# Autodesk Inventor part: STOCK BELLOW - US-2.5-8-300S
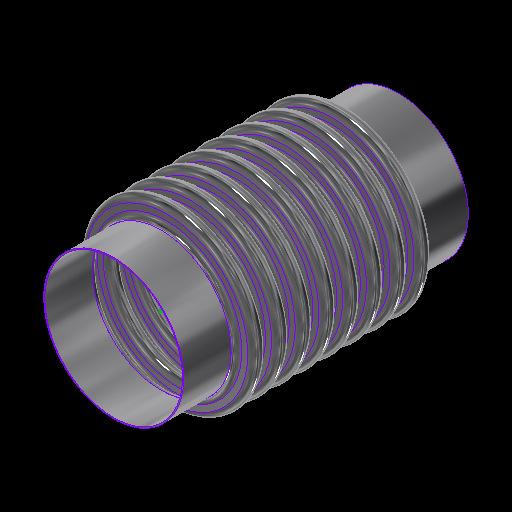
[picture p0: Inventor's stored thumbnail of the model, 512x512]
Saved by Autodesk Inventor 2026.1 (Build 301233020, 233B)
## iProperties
Category: 24 GA (0.024 THICK)
RuleStatus: InUse
Created: 2024-01
Part Number: STOCK BELLOW - US-2.5-8-300S
Project: =STOCK BELLOWS: <Stock Number><SFILL>
Material: ASTM A240-304
Description: =STOCK BELLOWS: <Stock Number>, <SID_> I.D., <SOD_> O.D., <SPLY_> PLY, <Category>, <SNET_CONS> CONS.<PITCH_><STANGENT_> TANGENT<SFILL>
Document SubType Name: Sheet Metal
Designer: GS
Stock Number: U.S-2.5-8-300S
Surface Area: 1355.78 cm^2
Volume: 41.0641 cm^3
Sheet Metal Rule: Default
Appearance: STAINLESS STEEL
Mass: 330.865 g
Density: 8.05729 g/cm^3
THK: 0.036
ID: 3.500
OD: 4.250
CONS_: 2
PITCH: 0.500
TANGENT: 0.500
BELLOWS_UPSET: 0.000
d79: 1.000
d82: 1.000
d83: 26.000
d84: 24.000
d174: 8
d214: 8
STHK_: 0.024
SID_: 2.900
SOD_: 3.700
SPITCH_: 0.500
STANGENT__: 1.000
SBELLOWS_UPSET_: 0.000
SDIFF_TAN: 1.000
d252: 2
d275: 2
d287: 0.050
d289: 0.500
d290: 0.000
SOD_NECK: 2 15/16
PLY: 1
PSET: 4.178
PBAR: 1.035
COUNTER: 1.500
NET_TUBE: 3.071
CONS: 2
S_CONS: 0
NET_CONS: 2
ID_M: 88.90 mm
OD_M: 107.95 mm
THK_M: 0.91 mm
ID_U: 3.500 in
OD_U: 4.250 in
THK_U: 0.036 in
TANGENT2: 0.500
TAN_TO_TAN: 1.000 in
d80: 2.571
d81: 10
SID: 2.375
SCONS_: 8
SPITCH: 0.250
STANGENT_: 1.000
SBELLOWS_UPSET: 0.000
SNET_CONS: 8
SS_CONS: 0
SCONS: 8
d190: 8
d191: 1
d192: 1
d193: 8
d194: 0
SIZE: 2.50
PRESSURE: 300
d230: 8
STANGENT: 4.000
SPLY_: 1
d233: 8
d234: 0
d263: 2
d265: 1
d268: 2
d269: 0
d286: 2
d288: 1
d291: 2
d292: 0
SREROLL: 0.750
BLETP: 0.000 ul
PRES_Copy: 85
MATTABLE: 20 GA (0.036 THICK)
PART_NUMBER: U.S-2.5-8-300S
PITCH_: =, <SPITCH_> PITCH,
CFILL: .
SFILL: .
MESH: ,
COMP: 0.77
EXT: 0.39
LAT: 0.30
ANG: 573
ASR: 1441
LSR: 1471
ANSR: 53
PRES: 300
COMPM: 7.7
EXTM: 3.85
LATM: 3.00
ASRM: 252.362
PRESM: 20.684
LSRM: 257.616
ANSRM: 9.282
TEMPMIN: 20
TEMPMAX: 800
TEMPMINM: -7
TEMPMAXM: 427
WEIGHTM: 0.331
WEIGHT: 0.729
Author: GS
Keywords: 20 GA (0.036 THICK)
Comments: =STOCK BELLOW - <STOCK NUMBER>
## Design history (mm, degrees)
sketch "Sketch2"
  geometry: L1 (0, -177.245)-(0, 562.856) reference; L2 (45.364, 0)-(44.45, 0); L3 (48.082, -2.718)-(50.343, -2.718); L4 (48.082, -3.632)-(50.343, -3.632); L5 (50.343, -9.982)-(48.082, -9.982); L6 (50.343, -9.068)-(48.082, -9.068); L7 (45.364, -12.7)-(44.45, -12.7); L8 (48.082, 0)-(48.082, -12.7); L9 (50.343, -6.35)-(53.975, -6.35); L10 (44.45, 0)-(44.45, -12.7); L11 (20.376, 102.841)-(20.376, 101.926); L12 (58.262, 457.127)-(58.262, 349.177); L13 (58.262, 444.427)-(58.262, 336.477); L14 (93.133, -58.817)-(93.133, -71.517); L15 (118.746, -66.401)-(118.746, -66.401); L16 (50.343, -9.068)-(50.343, -9.982); L17 (48.082, -9.068)-(48.082, -9.982); L18 (48.082, -9.525)-(50.343, -9.525); L19 (53.975, 0)-(53.975, -12.7); L20 (-50.343, -9.068)-(-50.343, -9.982); L21 (-50.343, -2.718)-(-48.082, -2.718); L22 (-50.343, -3.632)-(-48.082, -3.632); L23 (-48.082, -9.068)-(-50.343, -9.068); L24 (-50.343, -9.525)-(-48.082, -9.525); L25 (-48.082, -9.982)-(-50.343, -9.982); L26 (-48.082, -9.068)-(-48.082, -9.982); L27 (-44.45, 0.653)-(-44.45, -12.047); L28 (-48.082, -6.35)-(-44.45, -6.35); L29 (-50.343, 0.653)-(-50.343, -12.7); L30 (-53.061, 0)-(-53.975, 0); L31 (-53.975, 0)-(-53.975, -12.7); L32 (-53.061, -12.7)-(-53.975, -12.7); A1 r 2.718 centre (48.082, 0) between (45.364, 0) and (48.082, -2.718); A2 r 3.632 centre (48.082, 0) between (44.45, 0) and (48.082, -3.632); A3 r 3.632 centre (50.343, -6.35) between (50.343, -9.982) and (50.343, -2.718); A4 r 2.718 centre (50.343, -6.35) between (50.343, -9.068) and (50.343, -3.632); A5 r 2.718 centre (48.082, -12.7) between (48.082, -9.982) and (45.364, -12.7); A6 r 3.632 centre (48.082, -12.7) between (48.082, -9.068) and (44.45, -12.7); A7 r 3.175 centre (50.343, -6.35) between (50.343, -9.525) and (53.518, -6.35); A8 r 3.175 centre (48.082, -12.7) between (48.082, -9.525) and (44.907, -12.7); A9 r 2.718 centre (-50.343, -12.7) between (-50.343, -9.982) and (-53.061, -12.7); A10 r 2.718 centre (-48.082, -6.35) between (-48.082, -9.068) and (-48.082, -3.632); A11 r 3.175 centre (-48.082, -6.35) between (-48.082, -9.525) and (-44.907, -6.35); A12 r 3.632 centre (-48.082, -6.35) between (-48.082, -9.982) and (-48.082, -2.718); A13 r 3.175 centre (-50.343, -12.7) between (-50.343, -9.525) and (-53.518, -12.7); A14 r 3.632 centre (-50.343, -12.7) between (-50.343, -9.068) and (-53.975, -12.7); A15 r 2.718 centre (-50.343, 0) between (-53.061, 0) and (-50.343, -2.718); A16 r 3.632 centre (-50.343, 0) between (-53.975, 0) and (-50.343, -3.632); 10 further points
  constraints: 62 end point, 38 point on circle, 20 tangent, 16 centre point, 12 parallel, 9 midpoint, 7 vertical, 6 coincident, 6 concentric, 6 point on line, 4 equal radius, 4 perpendicular, 3 horizontal, 1 collinear, 1 horizontal alignment, 10 other
  dimensions: "THK" = 0.9144 distance of L11.start L11.end; "ID" = 88.9 distance of L11.end point (20.376, 13.026); "OD" = 107.95 distance of L12.start L12.end; "PITCH" = 12.7 distance of L12.start L13.start; "TANGENT" = 12.7 distance of L14.start L14.end; "BELLOWS_UPSET" = 0 distance of L15.start L15.end; "d43" = 88.9 diameter of L10 L1 (= ID); "d44" = 107.95 diameter of L9.end L1 (= OD); "d45" = 0.9144 distance between parallel lines of L5 L6 (computed from THK, PLY); "d46" = 3.6322 radius of A3 (computed from PITCH, THK, PLY); "UPSET_PITCH" = 12.7 distance of L2.end L7.end (derived); "SIDEWALL_ANGLE" = 360 deg dimension on L3 L9 (derived); "CON_GAP" = 5.4356 distance of point (48.082, -9.068) point (48.082, -3.632) (derived); "TAN1" = 4.98728 dimension on A8 (derived); "TAN2" = 4.98728 dimension on A7 (derived); "LEG1" = 2.2606 distance of L18.start L18.end (derived); "d278" = 0.9144 distance between parallel lines of L25 L23 (derived); "d279" = 3.6322 radius of A12 (derived); "d280" = 12.7 distance of L30.end L31.end (derived); "d281" = 360 deg dimension on L21 L28 (derived); "d282" = 5.4356 distance of point (-50.343, -9.068) point (-50.343, -3.632) (derived); "d283" = 4.98728 dimension on A13 (derived); "d284" = 4.98728 dimension on A11 (derived); "d285" = 2.2606 distance of L24.start L24.end (derived); "d293" = 88.9 diameter of L27 L1 (derived); "d294" = 107.95 diameter of L31 L1 (derived)
  node "Sketch Rectangular Pattern1" dims "d31" = 25.4, "ID" = 88.9
  node "Sketch Rectangular Pattern2" dims "d39" = 25.4, "PITCH" = 12.7
revolve "CONS" stored, may be unused: angle "d48" = 90 deg
node "BELLOW MIDPLANE"
pattern_linear "Rectangular Pattern2" dims "d52" = 12.7 (= UPSET_PITCH)
sketch "Sketch5"
  geometry: C1 r 45.364 at (0, 0) reference; C2 r 44.45 at (0, 0) reference
extrude "TANGENT" new body sketch "Sketch5" distance "d53" = 12.7 (= TANGENT); taper "d54" = 0 deg
revolve "SAMETAN" stored, may be unused: angle "d65" = 90 deg
revolve "DIFFTAN" stored, may be unused: angle "d70" = 90 deg
sketch "Sketch9"
  geometry: L1 (53.319, 0)-(-53.319, 0) reference; L2 (0, -17.78)-(0, 17.78) reference; L3 (38.085, 0)-(-38.085, 0); L4 (38.085, -11.906)-(38.085, 11.906); L5 (25.385, -11.906)-(25.385, 11.906); L6 (13.15, 11.906)-(13.15, -11.906); L7 (-25.385, -11.906)-(-25.385, 11.906); L8 (-38.085, -11.906)-(-38.085, 11.906); L9 (37.291, -11.906)-(37.291, 11.906); L10 (38.085, -11.906)-(37.291, -11.906); L11 (38.085, 11.906)-(37.291, 11.906); L12 (13.546, 11.906)-(12.753, 11.906); L13 (12.753, 11.906)-(12.753, -11.906); L14 (12.753, -11.906)-(13.546, -11.906); L15 (13.546, -11.906)-(13.546, 11.906); L16 (-13.546, 11.906)-(-13.546, -11.906); L17 (-13.15, 11.906)-(-13.15, -11.906); L18 (-13.546, -11.906)-(-12.753, -11.906); L19 (-12.753, -11.906)-(-12.753, 11.906); L20 (-12.753, 11.906)-(-13.546, 11.906); L21 (-38.085, -11.906)-(-37.291, -11.906); L22 (-37.291, -11.906)-(-37.291, 11.906); L23 (-37.291, 11.906)-(-38.085, 11.906); L24 (-38.085, 11.906)-(-38.085, -11.906); L25 (38.085, -0.397)-(-38.085, -0.397); L26 (-38.085, -0.397)-(-38.085, 0.397); L27 (-38.085, 0.397)-(38.085, 0.397); L28 (38.085, 0.397)-(38.085, -0.397); L29 (-38.085, 11.906)-(38.085, 11.906); L30 (38.085, 11.906)-(38.085, 12.7); L31 (38.085, 12.7)-(-38.085, 12.7); L32 (-38.085, 12.7)-(-38.085, 11.906); L33 (38.085, -11.906)-(-38.085, -11.906); L34 (-38.085, -11.906)-(-38.085, -12.7); L35 (-38.085, -12.7)-(38.085, -12.7); L36 (38.085, -12.7)-(38.085, -11.906); 30 further points
  constraints: 68 end point, 13 midpoint, 13 parallel, 8 horizontal, 7 perpendicular, 6 equal length, 3 point on line, 2 vertical, 14 other
  dimensions: "d115" = 23.8125 distance of L4.start L4.end (derived); "d116" = 12.7 distance between parallel lines of L4 L5 (derived); "d117" = 12.23516 distance between parallel lines of L5 L6 (derived); "d125" = 38.53427 distance between parallel lines of L7 L6 (derived); "d127" = 12.7 distance between parallel lines of L8 L7 (derived); "d128" = 24.93516 distance between parallel lines of L6 L4 (derived); "d130" = 76.16943 distance between parallel lines of L8 L4 (derived); "RULER_THK" = 0.79375 distance between parallel lines of L4 L9; "d135" = 0.79375 distance of L13.end L14.end (derived); "d138" = 26.29911 distance of L13.end L16.end (derived); "d143" = 0.79375 distance of L22.end L8.end (derived); "d144" = 0.79375 distance between parallel lines of L27 L25 (derived)
extrude "RULER" join sketch "Sketch9" distance "d149" = 0.79375 (derived); taper "d150" = 0 deg
extrude "BARS" join sketch "Sketch9" distance "d151" = 0.79375 (derived); taper "d152" = 0 deg
pattern_linear "Rectangular Pattern4" dims "d155" = 26.29911 (derived)
sketch "Sketch13"
  geometry: L1 (93.149, -52.467)-(93.149, -77.867); L2 (37.44, 0)-(36.83, 0); L3 (37.44, -12.7)-(36.83, -12.7); L4 (43.51, -9.83)-(40.31, -9.83); L5 (43.51, -9.22)-(40.31, -9.22); L6 (43.51, -6.35)-(46.99, -6.35); L7 (40.31, -2.87)-(43.51, -2.87); L8 (40.31, 0)-(40.31, -12.7); L9 (36.83, 0)-(36.83, -12.7); L10 (58.254, -402.451)-(58.254, -496.431); L11 (58.254, -415.151)-(58.254, -509.131); L12 (58.254, -440.551)-(58.254, -534.531); L13 (58.254, -453.251)-(58.254, -547.231); L14 (58.254, -465.951)-(58.254, -559.931); L15 (58.254, -478.651)-(58.254, -572.631); L16 (58.254, -491.351)-(58.254, -585.331); L17 (58.254, -427.851)-(58.254, -521.831); L18 (20.376, 102.536)-(20.376, 101.926); L19 (40.31, -3.48)-(43.51, -3.48); L20 (0, -722.904)-(0, 240.109) reference; L21 (-23.752, 0)-(142.514, 0) reference; A1 r 2.87 centre (40.31, 0) between (37.44, 0) and (40.31, -2.87); A2 r 2.87 centre (40.31, -12.7) between (40.31, -9.83) and (37.44, -12.7); A3 r 3.48 centre (40.31, -12.7) between (40.31, -9.22) and (36.83, -12.7); A4 r 2.87 centre (43.51, -6.35) between (43.51, -9.22) and (43.51, -3.48); A5 r 3.48 centre (43.51, -6.35) between (43.51, -9.83) and (43.51, -2.87); A6 r 3.48 centre (40.31, 0) between (36.83, 0) and (40.31, -3.48); 6 further points; 1 other entity
  constraints: 38 end point, 15 point on circle, 9 tangent, 6 centre point, 6 parallel, 5 vertical alignment, 4 point on line, 4 vertical, 3 coincident, 3 concentric, 2 collinear, 2 equal radius, 1 horizontal, 1 perpendicular, 23 other
  dimensions: "SBELLOWS_UPSET_" = 0 distance of point (118.762, -66.401) point (118.762, -66.401); "STOTAL_THK_BELLOW__" = 0.6096 distance between parallel lines of L4 L5 (derived); "d224" = 3.4798 radius of A5 (derived); "d225" = 12.7 distance of L2.end L3.end (derived); "SSIDEWALL_ANGLE_" = 0 deg angle of L7 L6 (derived); "SSCON_GAP_" = 5.7404 distance of point (40.31, -9.22) point (40.31, -3.48) (derived); "d235" = 73.66 diameter of L9 L20 (derived); "d236" = 93.98 diameter of L6.end L20 (derived)
  node "Sketch Rectangular Pattern4" dims "d228" = 25.4
  node "Sketch Rectangular Pattern5" dims "d229" = 25.4
revolve "SBELLOW" stored, may be unused: angle "d197" = 90 deg
pattern_linear "Rectangular Pattern5" dims "d204" = 12.7 (derived)
revolve "STANGENT" stored, may be unused: angle "d240" = 90 deg
revolve "SSAMETAN" stored, may be unused: angle "d241" = 90 deg
revolve "SDIFFTAN" stored, may be unused: angle "d246" = 90 deg
revolve "INVCON" stored, may be unused: angle "d295" = 90 deg
pattern_linear "Rectangular Pattern6" dims "d298" = 12.7 (derived)
revolve "INVTANGENT" stored, may be unused: angle "d302" = 90 deg
revolve "INVSAMETAN" stored, may be unused: angle "d307" = 90 deg
revolve "INVDIFFTAN" stored, may be unused: angle "d312" = 90 deg
sketch "ID BELLOW MOUNT CALC"
  geometry: L1 (44.45, 0)-(38.1, 0); L2 (38.1, 0)-(38.1, 12.7); L3 (38.1, 12.7)-(44.45, 12.7); L4 (44.45, 12.7)-(44.45, 0); L5 (36.513, 12.7)-(35.598, 12.7); L6 (35.598, 12.7)-(35.598, 0); L7 (35.598, 0)-(36.513, 0); L8 (36.513, 0)-(36.513, 12.7); L9 (0, -2.54)-(0, 15.24) reference; L10 (-8.89, 0)-(53.34, 0) reference; 1 further point
  constraints: 16 end point, 5 parallel, 2 collinear, 2 horizontal, 2 perpendicular
  dimensions: "d314" = 12.7 distance of L5.end L6.end (derived); "d315" = 0.9144 distance of L5.start L5.end (derived); "IG" = 1.5875 distance between parallel lines of L2 L8; "PIPE_OD" = 88.9 diameter of L4 L9; "PIPE_WALL" = 6.35 distance of L2.end L3.end; "ID_MT_BELLOW" = 71.1962 diameter of L6 L9 (derived)
revolve "CFILL" stored, may be unused: angle "d320" = 90 deg
pattern_linear "Rectangular Pattern7" dims "d323" = 12.7 (derived)
revolve "SFILL" stored, may be unused: angle "d324" = 90 deg
pattern_linear "Rectangular Pattern8" dims "d327" = 12.7 (derived)
node "STOCK BELLOW MIDPLANE"
node "BELLOW"
sketch "Sketch6"
  geometry: L1 (-12.7, 45.364)-(0, 45.364); L2 (0, 45.364)-(0, 44.45); L3 (0, 44.45)-(-12.7, 44.45); L4 (-12.7, 44.45)-(-12.7, 45.364); L5 (10.16, 0)-(-60.96, 0) reference; L6 (-38.1, -89.422)-(-38.1, 153.44) reference; 1 further point
  constraints: 8 end point, 2 parallel, 1 horizontal, 1 perpendicular
  dimensions: "d61" = 12.7 distance of L2.end L3.end (derived); "d62" = 0.9144 distance of L1.end L2.end (derived); "d63" = 88.9 diameter of L3 L5 (derived); "d64" = 25.4 distance between parallel lines of L4 L6 (derived)
sketch "Sketch12"
  geometry: 1 further point
sketch "Sketch14"
  geometry: L1 (-25.4, 37.44)-(0, 37.44); L2 (0, 37.44)-(0, 36.83); L3 (0, 36.83)-(-25.4, 36.83); L4 (-25.4, 36.83)-(-25.4, 37.44); L5 (5.08, 0)-(-30.48, 0) reference; L6 (0, -8.89)-(0, 53.34) reference; 1 further point
  constraints: 8 end point, 2 parallel, 1 collinear, 1 horizontal, 1 perpendicular
  dimensions: "d237" = 0.6096 distance of L3.end L1.start (derived); "d238" = 73.66 diameter of L3 L5 (derived); "d239" = 25.4 distance of L1.start L1.end (derived); "SOD_NECK" = 74.8792 diameter of L1 L5 (derived)
sketch "Sketch15"
  geometry: L1 (-8.89, 0)-(53.34, 0) reference; L2 (36.83, -101.6)-(37.44, -101.6); L3 (37.44, -101.6)-(37.44, -127); L4 (37.44, -127)-(36.83, -127); L5 (36.83, -127)-(36.83, -101.6); L6 (0, -154.94)-(0, 40.64) reference; 1 further point
  constraints: 8 end point, 2 parallel, 1 horizontal, 1 perpendicular
  dimensions: "d205" = 25.4 distance of L4.end L2.start (derived); "d206" = 0.6096 distance of L3.end L4.end (derived); "d207" = 73.66 diameter of L5 L6 (derived); "d208" = 101.6 distance between parallel lines of L1 L2 (derived)
node "TANGENT_"
node "SAME_TAN"
sketch "Sketch8"
  geometry: L1 (45.364, -25.4)-(44.45, -25.4); L2 (44.45, -25.4)-(44.45, -38.1); L3 (44.45, -38.1)-(45.364, -38.1); L4 (45.364, -38.1)-(45.364, -25.4); L5 (0, -48.26)-(0, 22.86) reference; L6 (-89.422, 0)-(153.44, 0) reference; 1 further point
  constraints: 8 end point, 2 parallel, 1 horizontal, 1 perpendicular
  dimensions: "d66" = 88.9 diameter of L2 L5 (derived); "TOTAL_THK_BELLOW" = 0.9144 distance of L2.end L3.end (derived); "d68" = 25.4 distance between parallel lines of L1 L6 (derived); "d69" = 12.7 distance of L1.end L2.end (derived)
node "DIFF_TAN"
node "Sketch Rectangular Pattern3" dims "d138" = 26.29911 (derived), "d141" = 25.4
node "SBELLOW_"
node "STANGENT_"
node "SSAME_TAN"
sketch "Sketch16"
  geometry: L1 (37.44, -101.6)-(36.83, -101.6); L2 (36.83, -101.6)-(36.83, -127); L3 (36.83, -127)-(37.44, -127); L4 (37.44, -127)-(37.44, -101.6); L5 (0, -154.94)-(0, 40.64) reference; L6 (-8.89, 0)-(53.34, 0) reference; 1 further point
  constraints: 8 end point, 2 parallel, 1 horizontal, 1 perpendicular
  dimensions: "SDIFF_TAN" = 25.4 distance of L3.end L1.start; "d243" = 0.6096 distance of L2.end L3.end (derived); "d244" = 101.6 distance between parallel lines of L1 L6 (derived); "d245" = 73.66 diameter of L2 L5 (derived)
node "SDIFF_TAN"
body "Solid15"
sketch "Sketch17"
  geometry: L1 (53.975, 12.7)-(53.061, 12.7); L2 (53.061, 12.7)-(53.061, 0); L3 (53.061, 0)-(53.975, 0); L4 (53.975, 0)-(53.975, 12.7); L5 (0, -2.54)-(0, 15.24) reference; L6 (-10.795, 0)-(64.77, 0) reference; 2 further points
  constraints: 8 end point, 2 parallel, 1 horizontal, 1 midpoint, 1 perpendicular, 1 point on line
  dimensions: "INVTANGENT" = 12.7 distance of L3.end L1.start (derived); "d300" = 0.9144 distance of L1.start L1.end (derived); "d301" = 107.95 diameter of L4 L5 (derived)
body "Solid16"
sketch "Sketch18"
  geometry: L1 (53.975, -25.4)-(53.061, -25.4); L2 (53.061, -25.4)-(53.061, -38.1); L3 (53.061, -38.1)-(53.975, -38.1); L4 (53.975, -38.1)-(53.975, -25.4); L5 (-10.795, 0)-(64.77, 0) reference; L6 (0, -48.26)-(0, 22.86) reference; 1 further point
  constraints: 8 end point, 2 parallel, 1 horizontal, 1 perpendicular
  dimensions: "d303" = 25.4 distance between parallel lines of L1 L5 (derived); "d304" = 12.7 distance of L3.end L1.start (derived); "d305" = 0.9144 distance of L2.end L3.end (derived); "d306" = 107.95 diameter of L4 L6 (derived)
body "Solid17"
sketch "Sketch19"
  geometry: L1 (53.975, -25.4)-(53.061, -25.4); L2 (53.061, -25.4)-(53.061, -38.1); L3 (53.061, -38.1)-(53.975, -38.1); L4 (53.975, -38.1)-(53.975, -25.4); L5 (0, -48.26)-(0, 22.86) reference; L6 (-10.795, 0)-(64.77, 0) reference; 1 further point
  constraints: 8 end point, 2 parallel, 1 horizontal, 1 perpendicular
  dimensions: "d308" = 12.7 distance of L1.end L2.end (derived); "d309" = 107.95 diameter of L4 L5 (derived); "d310" = 0.9144 distance of L2.end L3.end (derived); "d311" = 25.4 distance between parallel lines of L1 L6 (derived)
body "Solid18"
body "Solid19"
body "Solid20"
other parameters: "BMPL" = -50.8, "PSET" = 106.1212 (computed from OD, THK, PLY) [user parameter], "PBAR" = 26.29911 (= 0.570796 x PITCH + OD - ID) [user parameter; used in 1 equation term], "COUNTER" = 15 [user parameter], "NET_TUBE" = 77.99823 (computed from CONS_, PBAR, TANGENT) [user parameter], "S_CONS" = 0 [user parameter; used in 1 equation term], "ID_M" = 88.9 (= ID) [user parameter], "OD_M" = 107.95 (= OD) [user parameter], "THK_M" = 0.9144 (= THK) [user parameter], "ID_U" = 88.9 (= ID) [user parameter], "OD_U" = 107.95 (= OD) [user parameter], "THK_U" = 0.9144 (= THK) [user parameter], "D_UNITS" = 0 [user parameter], "TANGENT2" = 12.7 [user parameter], "TAN_TO_TAN" = 25.4 [user parameter], "OD_NECK" = 90.7288 [user parameter], "d79" = 25.4, "d80" = 65.29823 [user parameter], "d82" = 25.4, "d83" = 660.4, "d84" = 609.6, "sa_0" = 4, "FRAME_THK" = 0.79375 [user parameter], "CON_FLAT" = 12.23516 [user parameter], "SID" = 60.325 [user parameter], "SPITCH" = 6.35 [user parameter], "STANGENT_" = 25.4 [user parameter], "SBELLOWS_UPSET" = 0 [user parameter], "SS_CONS" = 0 [user parameter], "STAN_TO_TAN_" = 101.6 [user parameter], "d100" = 0.6096 [user parameter], "d191" = 25.4 [user parameter], "d194" = 0 [user parameter], "STANGENT" = 101.6 [user parameter], "d234" = 0 [user parameter], "SUPSET_PITCH_" = 12.7 [user parameter], "d269" = 0 [user parameter], "d287" = 1.27, "d289" = 12.7, "d290" = 0, "d292" = 0 [user parameter], "Thickness" = 3.048 (derived), "KFactor" = 4.4, "BendRadius" = 3.048 (derived), "BendReliefWidth" = 3.048 (derived), "BendReliefDepth" = 1.524 (derived), "CornerReliefSize" = 12.192 (derived), "SeamGap" = 0.00508, "MinimumRemnant" = 6.096 (derived), "TransitionRadius" = 3.048 (derived), "JacobiRadiusSize" = 3.048 (derived), "GapSize" = 3.048 (derived), "SREROLL" = 19.05 [user parameter], "CUR_STK_PITCH" = 12.7 [user parameter], "d328" = -50.8 (derived), "ASR" = 14410 [user parameter], "LSR" = 14710 [user parameter], "BLETP" = 0 [user parameter], "ASRM" = 2523.6233 [user parameter], "PRESM" = 206.83949 [user parameter], "LSRM" = 2576.1623 [user parameter], "ANSRM" = 92.8189 [user parameter], "TEMPMIN" = 2664.83333 [user parameter], "TEMPMAX" = 6998.16667 [user parameter], "TEMPMINM" = 2664.83333 [user parameter], "TEMPMAXM" = 6998.16667 [user parameter], "WEIGHT" = 3.30865 [user parameter], "WEIGHTM" = 0.00331 [user parameter]
